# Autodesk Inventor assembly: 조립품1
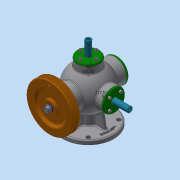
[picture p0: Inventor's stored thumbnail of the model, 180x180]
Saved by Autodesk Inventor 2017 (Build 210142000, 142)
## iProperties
Part Number: 조립품1
Material: 일반
Document SubType Name: Assembly
Designer: MRC
Author: MRC
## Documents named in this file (17)
- C:\Users\MRC\Desktop\600911V1007\조립품1.iam
- C:\Users\MRC\Desktop\600911V1007\V-벨트풀리.ipt
- C:\Users\MRC\Desktop\600911V1007\너트 M8x1.ipt
- C:\Users\MRC\Desktop\600911V1007\뒤커버.ipt
- C:\Users\MRC\Desktop\600911V1007\베어링 6202.ipt
- C:\Users\MRC\Desktop\600911V1007\본체.ipt
- C:\Users\MRC\Desktop\600911V1007\본체커버.ipt
- C:\Users\MRC\Desktop\600911V1007\볼트 M4.ipt
- C:\Users\MRC\Desktop\600911V1007\스프링1.ipt
- C:\Users\MRC\Desktop\600911V1007\스프링2.ipt
- C:\Users\MRC\Desktop\600911V1007\슬라이드 커버.ipt
- C:\Users\MRC\Desktop\600911V1007\슬라이드.ipt
- C:\Users\MRC\Desktop\600911V1007\앞커버.ipt
- C:\Users\MRC\Desktop\600911V1007\오일 실.ipt
- C:\Users\MRC\Desktop\600911V1007\와셔 8x17.ipt
- C:\Users\MRC\Desktop\600911V1007\축.ipt
- C:\Users\MRC\Desktop\600911V1007\키 4x4.ipt
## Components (1 placed, 1 different names)
1. V-벨트풀리:1
